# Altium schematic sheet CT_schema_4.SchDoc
size 205 x 258 mm
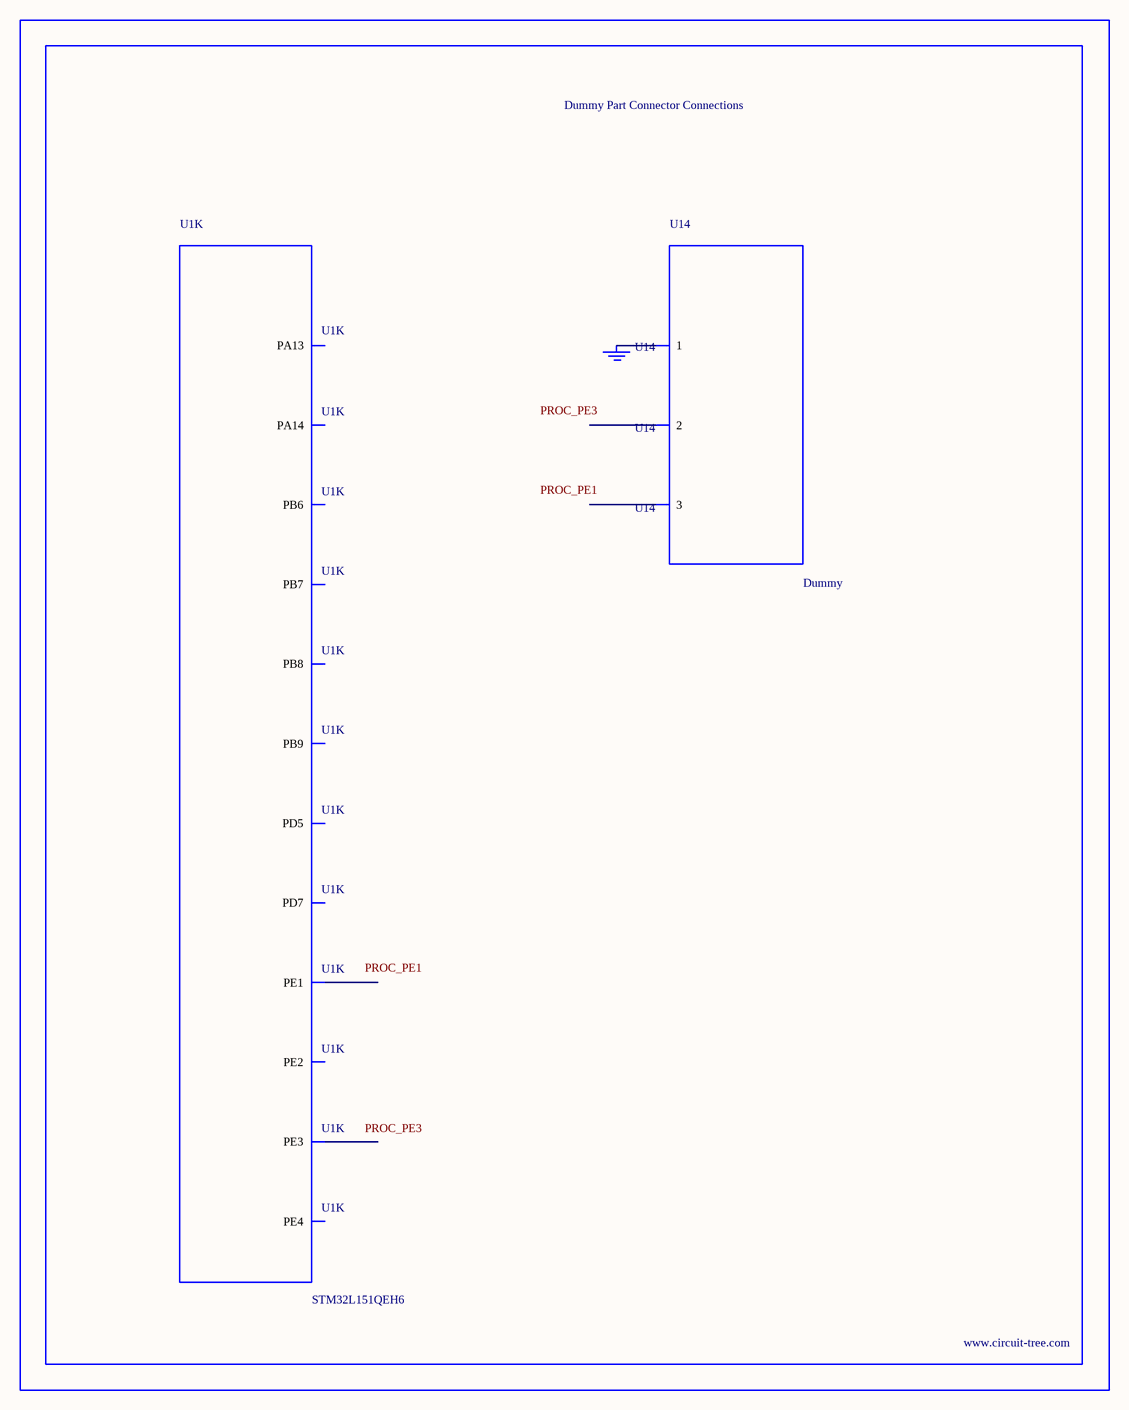
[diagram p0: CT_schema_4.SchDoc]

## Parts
BORDER3  (no value)
GND_INSTANCE_3_0  (no value)
U1  STM32L151QEH6  [UFBGA132]  (part K of 11)
U14  Dummy  [DUMMY_PACKAGE_117]

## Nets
NetGND_INSTANCE_3_0_0: GND_INSTANCE_3_0.0(GND) U14.1

Not connected (* = marked no-connect by the designer): U1 A1(PE3) A2(PE1) A3(PB8) A5(PD7) A6(PD5) A10(PA14) A11(PA13) B1(PE4) B2(PE2) B3(PB9) B4(PB7) B5(PB6); U14 2 3

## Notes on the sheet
- Labels drawn without touching a wire or pin: PROC_PE1, PROC_PE3

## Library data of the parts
BORDER3 = BORDER_PAGE3
GND_INSTANCE_3_0 = GND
